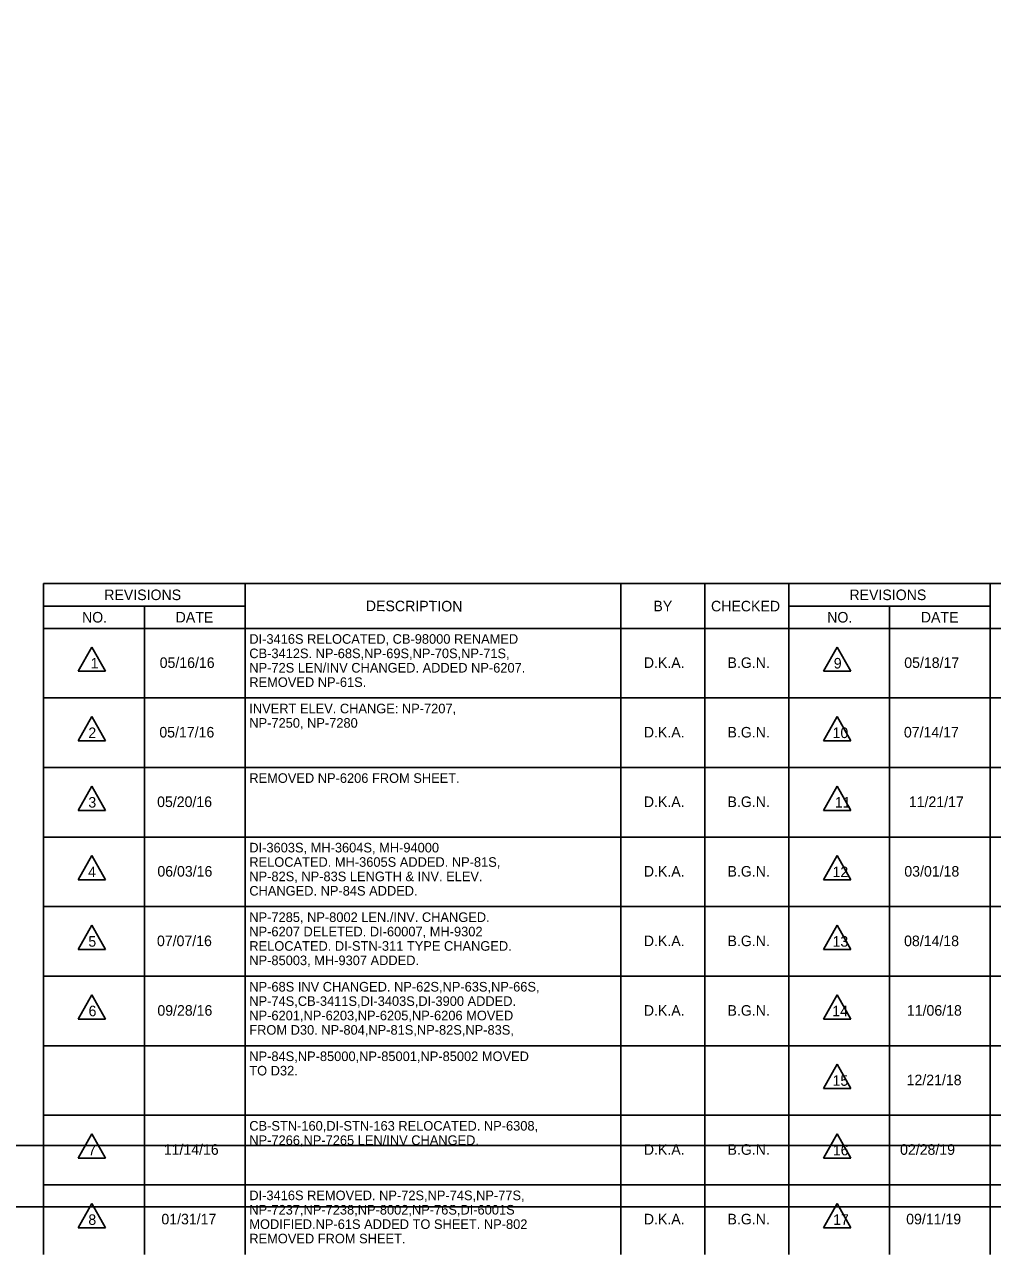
# Model space of a CAD drawing. Extents: x 260980 to 262786, y 322332 to 323393.
# Drawn here: x 261936 to 262340, y 322332 to 322845 of the extents above; entities that cross this region are included whole.
import ezdxf

# ---------------------------------------------------------------- set-up
doc = ezdxf.new("R2010")
doc.units = 0
for name, color, linetype in [('Level 23', 7, 'Continuous'), ('Level 5', 7, 'Continuous'), ('RD_SHT_TX', 7, 'Continuous')]:
    doc.layers.add(name, color=color, linetype=linetype)

msp = doc.modelspace()

# ---------------------------------------------------------------- linework, layer by layer
at = {"layer": 'Level 23'}
msp.add_lwpolyline([(261111.06, 323336.45), (262761.54, 323336.45), (262761.54, 322351.79), (261111.06, 322351.79)], close=True, dxfattribs=at)
msp.add_lwpolyline([(261111.06, 323336.45), (262761.54, 323336.45), (262761.54, 322351.79), (261111.06, 322351.79)], close=True, dxfattribs=at)
at = {"layer": 'Level 5'}
msp.add_lwpolyline([(261111.06, 323310.45), (262762.33, 323310.45), (262762.33, 322377.34), (261111.06, 322377.34)], close=True, dxfattribs=at)
at = {"layer": 'RD_SHT_TX'}
for p, q in [((261944.02, 322331.93), (261944.02, 322611.63)), ((261944.02, 322611.63), (262254.62, 322611.63)), ((262028.02, 322331.93), (262028.02, 322611.63)), ((262184.62, 322331.93), (262184.62, 322611.63)), ((262219.62, 322331.93), (262219.62, 322611.63)), ((262254.62, 322331.93), (262254.62, 322611.63)), ((262254.62, 322611.63), (262565.22, 322611.63)), ((262338.62, 322331.93), (262338.62, 322611.63)), ((262028.02, 322602.28), (261944.02, 322602.28)), ((261986.02, 322331.93), (261986.02, 322602.28)), ((262338.62, 322602.28), (262254.62, 322602.28)), ((262296.62, 322331.93), (262296.62, 322602.28)), ((262565.22, 322592.93), (261944.02, 322592.93)), ((261964.18, 322585.19), (261958.49, 322575.05)), ((261969.88, 322575.05), (261964.18, 322585.19)), ((262274.78, 322585.19), (262269.09, 322575.05)), ((262280.48, 322575.05), (262274.78, 322585.19)), ((261958.49, 322575.05), (261969.88, 322575.05)), ((262269.09, 322575.05), (262280.48, 322575.05)), ((262565.22, 322563.93), (261944.02, 322563.93)), ((262565.22, 322563.93), (261944.02, 322563.93)), ((261964.18, 322556.19), (261958.49, 322546.05)), ((261969.88, 322546.05), (261964.18, 322556.19)), ((262274.78, 322556.19), (262269.09, 322546.05)), ((262280.48, 322546.05), (262274.78, 322556.19)), ((261958.49, 322546.05), (261969.88, 322546.05)), ((262269.09, 322546.05), (262280.48, 322546.05)), ((262565.22, 322534.93), (261944.02, 322534.93)), ((261964.18, 322527.19), (261958.49, 322517.05)), ((261969.88, 322517.05), (261964.18, 322527.19)), ((262274.78, 322527.19), (262269.09, 322517.05)), ((262280.48, 322517.05), (262274.78, 322527.19)), ((261958.49, 322517.05), (261969.88, 322517.05)), ((262269.09, 322517.05), (262280.48, 322517.05)), ((262565.22, 322505.93), (261944.02, 322505.93)), ((261964.18, 322498.19), (261958.49, 322488.05)), ((261969.88, 322488.05), (261964.18, 322498.19)), ((262274.78, 322498.19), (262269.09, 322488.05)), ((262280.48, 322488.05), (262274.78, 322498.19)), ((261958.49, 322488.05), (261969.88, 322488.05)), ((262269.09, 322488.05), (262280.48, 322488.05)), ((262565.22, 322476.93), (261944.02, 322476.93)), ((261964.18, 322469.19), (261958.49, 322459.05)), ((261969.88, 322459.05), (261964.18, 322469.19)), ((262274.78, 322469.19), (262269.09, 322459.05)), ((262280.48, 322459.05), (262274.78, 322469.19)), ((261958.49, 322459.05), (261969.88, 322459.05)), ((262269.09, 322459.05), (262280.48, 322459.05)), ((262565.22, 322447.93), (261944.02, 322447.93)), ((261964.18, 322440.19), (261958.49, 322430.05)), ((261969.88, 322430.05), (261964.18, 322440.19)), ((262274.78, 322440.19), (262269.09, 322430.05)), ((262280.48, 322430.05), (262274.78, 322440.19)), ((261958.49, 322430.05), (261969.88, 322430.05)), ((262269.09, 322430.05), (262280.48, 322430.05)), ((262565.22, 322418.93), (261944.02, 322418.93)), ((262274.78, 322411.19), (262269.09, 322401.05)), ((262280.48, 322401.05), (262274.78, 322411.19)), ((262269.09, 322401.05), (262280.48, 322401.05)), ((262565.22, 322389.93), (261944.02, 322389.93)), ((261964.18, 322382.19), (261958.49, 322372.05)), ((261969.88, 322372.05), (261964.18, 322382.19)), ((262274.78, 322382.19), (262269.09, 322372.05)), ((262280.48, 322372.05), (262274.78, 322382.19)), ((261958.49, 322372.05), (261969.88, 322372.05)), ((262269.09, 322372.05), (262280.48, 322372.05)), ((262565.22, 322360.93), (261944.02, 322360.93)), ((261964.18, 322353.19), (261958.49, 322343.05)), ((261969.88, 322343.05), (261964.18, 322353.19)), ((262274.78, 322353.19), (262269.09, 322343.05)), ((262280.48, 322343.05), (262274.78, 322353.19)), ((261958.49, 322343.05), (261969.88, 322343.05)), ((262269.09, 322343.05), (262280.48, 322343.05))]:
    msp.add_line(p, q, dxfattribs=at)

# ---------------------------------------------------------------- texts
for s, p in [('REVISIONS', (261969.31, 322604.75)), ('CHECKED', (262222.22, 322600.05)), ('REVISIONS', (262279.91, 322604.75)), ('NO.', (261960.04, 322595.4)), ('NO.', (262270.64, 322595.4)), ('1', (261963.65, 322576.23)), ('9', (262273.38, 322576.23)), ('2', (261962.68, 322547.23)), ('10', (262272.9, 322547.23)), ('3', (261962.68, 322518.23)), ('11', (262273.84, 322518.23)), ('4', (261962.57, 322489.23)), ('12', (262272.87, 322489.23)), ('5', (261962.68, 322460.23)), ('13', (262272.87, 322460.23)), ('6', (261962.78, 322431.23)), ('14', (262272.76, 322431.23)), ('15', (262272.87, 322402.23)), ('7', (261962.64, 322373.23)), ('16', (262273, 322373.23)), ('8', (261962.68, 322344.23)), ('17', (262273.11, 322344.23))]:
    msp.add_text(s, height=4.4, dxfattribs=at).set_placement(p)
for s, height, rotation, p in [('DESCRIPTION', 4.4083, 359.7246, (262078.32, 322600.17)), ('BY', 4.408, 359.7246, (262198.18, 322600.09)), ('DATE', 4.408, 359.7246, (261999.05, 322595.43)), ('DATE', 4.408, 359.7246, (262309.65, 322595.43)), ('DI-3416S RELOCATED, CB-98000 RENAMED', 4, 360, (262029.77, 322586.54)), ('CB-3412S. NP-68S,NP-69S,NP-70S,NP-71S,', 4, 360, (262029.77, 322580.54)), ('05/16/16', 4.4, 360, (261992.41, 322576.46)), ('D.K.A.', 4.4, 360, (262194.21, 322576.46)), ('B.G.N.', 4.4, 360, (262229.09, 322576.46)), ('05/18/17', 4.4, 360, (262302.76, 322576.46)), ('NP-72S LEN/INV CHANGED. ADDED NP-6207.', 4, 360, (262029.77, 322574.54)), ('REMOVED NP-61S.', 4, 360, (262029.77, 322568.54)), ('INVERT ELEV. CHANGE: NP-7207,', 4, 360, (262029.77, 322557.54)), ('NP-7250, NP-7280', 4, 360, (262029.77, 322551.54)), ('05/17/16', 4.4, 360, (261992.27, 322547.46)), ('D.K.A.', 4.4, 360, (262194.21, 322547.46)), ('B.G.N.', 4.4, 360, (262229.08, 322547.46)), ('07/14/17', 4.4, 360, (262302.62, 322547.46)), ('REMOVED NP-6206 FROM SHEET.', 4, 360, (262029.77, 322528.54)), ('05/20/16', 4.4, 360, (261991.34, 322518.46)), ('D.K.A.', 4.4, 360, (262194.21, 322518.46)), ('B.G.N.', 4.4, 360, (262229.09, 322518.46)), ('11/21/17', 4.4, 360, (262304.67, 322518.46)), ('DI-3603S, MH-3604S, MH-94000', 4, 360, (262029.77, 322499.54)), ('RELOCATED. MH-3605S ADDED. NP-81S,', 4, 360, (262029.77, 322493.54)), ('06/03/16', 4.4, 360, (261991.45, 322489.46)), ('D.K.A.', 4.4, 360, (262194.21, 322489.46)), ('B.G.N.', 4.4, 360, (262229.09, 322489.46)), ('03/01/18', 4.4, 360, (262302.79, 322489.46)), ('NP-82S, NP-83S LENGTH & INV. ELEV.', 4, 360, (262029.77, 322487.54)), ('CHANGED. NP-84S ADDED.', 4, 360, (262029.77, 322481.54)), ('NP-7285, NP-8002 LEN./INV. CHANGED.', 4, 360, (262029.77, 322470.54)), ('NP-6207 DELETED. DI-60007, MH-9302', 4, 360, (262029.77, 322464.54)), ('07/07/16', 4.4, 360, (261991.27, 322460.46)), ('RELOCATED. DI-STN-311 TYPE CHANGED.', 4, 360, (262029.77, 322458.54)), ('D.K.A.', 4.4, 360, (262194.21, 322460.46)), ('B.G.N.', 4.4, 360, (262229.09, 322460.46)), ('08/14/18', 4.4, 360, (262302.69, 322460.46)), ('NP-85003, MH-9307 ADDED.', 4, 360, (262029.77, 322452.54)), ('NP-68S INV CHANGED. NP-62S,NP-63S,NP-66S,', 4, 360, (262029.77, 322441.54)), ('09/28/16', 4.4, 360, (261991.45, 322431.46)), ('NP-74S,CB-3411S,DI-3403S,DI-3900 ADDED.', 4, 360, (262029.77, 322435.54)), ('D.K.A.', 4.4, 360, (262194.21, 322431.46)), ('B.G.N.', 4.4, 360, (262229.09, 322431.46)), ('11/06/18', 4.4, 360, (262303.86, 322431.46)), ('NP-6201,NP-6203,NP-6205,NP-6206 MOVED', 4, 360, (262029.77, 322429.54)), ('FROM D30. NP-804,NP-81S,NP-82S,NP-83S,', 4, 360, (262029.77, 322423.54)), ('NP-84S,NP-85000,NP-85001,NP-85002 MOVED', 4, 360, (262029.77, 322412.54)), ('TO D32.', 4, 360, (262029.77, 322406.54)), ('12/21/18', 4.4, 360, (262303.75, 322402.46)), ('CB-STN-160,DI-STN-163 RELOCATED. NP-6308,', 4, 360, (262029.77, 322383.54)), ('NP-7266,NP-7265 LEN/INV CHANGED.', 4, 360, (262029.77, 322377.54)), ('11/14/16', 4.4, 360, (261994.11, 322373.46)), ('D.K.A.', 4.4, 360, (262194.21, 322373.46)), ('B.G.N.', 4.4, 360, (262229.09, 322373.46)), ('02/28/19', 4.4, 360, (262301.02, 322373.46)), ('DI-3416S REMOVED. NP-72S,NP-74S,NP-77S,', 4, 360, (262029.77, 322354.54)), ('01/31/17', 4.4, 360, (261993.12, 322344.46)), ('NP-7237,NP-7238,NP-8002,NP-76S,DI-6001S', 4, 360, (262029.77, 322348.54)), ('D.K.A.', 4.4, 360, (262194.21, 322344.46)), ('B.G.N.', 4.4, 360, (262229.09, 322344.46)), ('09/11/19', 4.4, 360, (262303.57, 322344.46)), ('MODIFIED.NP-61S ADDED TO SHEET. NP-802', 4, 360, (262029.77, 322342.54)), ('REMOVED FROM SHEET.', 4, 360, (262029.77, 322336.54))]:
    msp.add_text(s, height=height, rotation=rotation, dxfattribs=at).set_placement(p)

doc.saveas('drawing.dxf')
